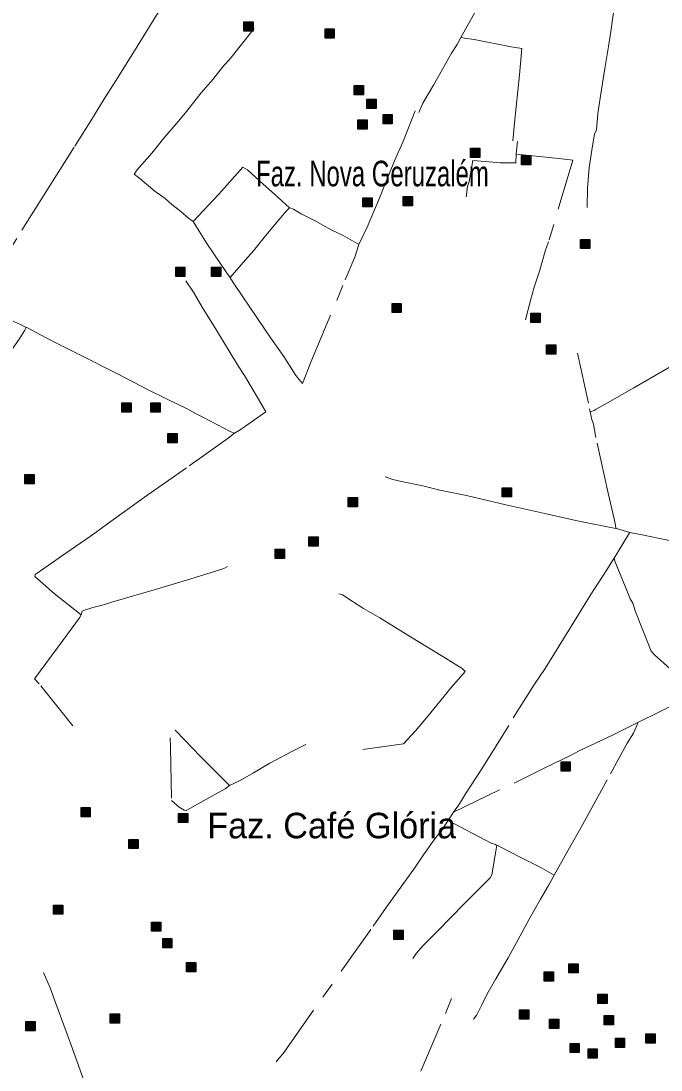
# Model space of a CAD drawing. Extents: x 393.5 to 446.9, y 8064.8 to 8120.4.
# Drawn here: x 428.9 to 432.91, y 8076.18 to 8082.75 of the extents above; entities that cross this region are included whole.
import ezdxf

# ---------------------------------------------------------------- set-up
doc = ezdxf.new("R2010")
doc.units = 0
doc.header["$LTSCALE"] = 0.064
doc.linetypes.add('DOT_DASHED', pattern=[7.7, 5, -1.2, 0.3, -1.2])
doc.layers.add('2', color=7, linetype='Continuous', lineweight=25)
doc.layers.add('22', color=7, linetype='DOT_DASHED', lineweight=13)
doc.layers.add('61', color=7, linetype='Continuous')

msp = doc.modelspace()

# ---------------------------------------------------------------- hatches: boundary and pattern name
at = {"layer": '2'}
for points in [[(430.2985, 8082.7404), (430.3565, 8082.7404), (430.3565, 8082.6824), (430.2985, 8082.6824)], [(430.8062, 8082.697), (430.8642, 8082.697), (430.8642, 8082.639), (430.8062, 8082.639)], [(430.9884, 8082.3419), (431.0464, 8082.3419), (431.0464, 8082.2839), (430.9884, 8082.2839)], [(431.0671, 8082.2575), (431.1251, 8082.2575), (431.1251, 8082.1995), (431.0671, 8082.1995)], [(431.1692, 8082.1613), (431.2272, 8082.1613), (431.2272, 8082.1033), (431.1692, 8082.1033)], [(431.0109, 8082.1278), (431.0689, 8082.1278), (431.0689, 8082.0698), (431.0109, 8082.0698)], [(431.7169, 8081.9496), (431.7749, 8081.9496), (431.7749, 8081.8916), (431.7169, 8081.8916)], [(432.0365, 8081.9048), (432.0945, 8081.9048), (432.0945, 8081.8468), (432.0365, 8081.8468)], [(431.0433, 8081.6399), (431.1013, 8081.6399), (431.1013, 8081.5819), (431.0433, 8081.5819)], [(431.2959, 8081.6468), (431.3539, 8081.6468), (431.3539, 8081.5888), (431.2959, 8081.5888)], [(432.4052, 8081.379), (432.4632, 8081.379), (432.4632, 8081.321), (432.4052, 8081.321)], [(429.8713, 8081.2049), (429.9293, 8081.2049), (429.9293, 8081.1469), (429.8713, 8081.1469)], [(430.0958, 8081.2046), (430.1538, 8081.2046), (430.1538, 8081.1466), (430.0958, 8081.1466)], [(431.2253, 8080.9782), (431.2833, 8080.9782), (431.2833, 8080.9202), (431.2253, 8080.9202)], [(432.095, 8080.9158), (432.153, 8080.9158), (432.153, 8080.8578), (432.095, 8080.8578)], [(432.193, 8080.719), (432.251, 8080.719), (432.251, 8080.661), (432.193, 8080.661)], [(429.5337, 8080.355), (429.5917, 8080.355), (429.5917, 8080.297), (429.5337, 8080.297)], [(429.7162, 8080.3548), (429.7742, 8080.3548), (429.7742, 8080.2968), (429.7162, 8080.2968)], [(429.8217, 8080.1627), (429.8797, 8080.1627), (429.8797, 8080.1047), (429.8217, 8080.1047)], [(428.9274, 8079.9055), (428.9854, 8079.9055), (428.9854, 8079.8475), (428.9274, 8079.8475)], [(431.9156, 8079.8236), (431.9736, 8079.8236), (431.9736, 8079.7656), (431.9156, 8079.7656)], [(430.9513, 8079.7613), (431.0093, 8079.7613), (431.0093, 8079.7033), (430.9513, 8079.7033)], [(430.7054, 8079.5158), (430.7634, 8079.5158), (430.7634, 8079.4578), (430.7054, 8079.4578)], [(430.4949, 8079.4389), (430.5529, 8079.4389), (430.5529, 8079.3809), (430.4949, 8079.3809)], [(432.2833, 8078.1064), (432.3413, 8078.1064), (432.3413, 8078.0484), (432.2833, 8078.0484)], [(429.279, 8077.8199), (429.337, 8077.8199), (429.337, 8077.7619), (429.279, 8077.7619)], [(429.8898, 8077.784), (429.9478, 8077.784), (429.9478, 8077.726), (429.8898, 8077.726)], [(429.5787, 8077.621), (429.6367, 8077.621), (429.6367, 8077.563), (429.5787, 8077.563)], [(429.106, 8077.2097), (429.164, 8077.2097), (429.164, 8077.1517), (429.106, 8077.1517)], [(429.7209, 8077.1034), (429.7789, 8077.1034), (429.7789, 8077.0454), (429.7209, 8077.0454)], [(431.2376, 8077.0524), (431.2956, 8077.0524), (431.2956, 8076.9944), (431.2376, 8076.9944)], [(429.7901, 8077.0005), (429.8481, 8077.0005), (429.8481, 8076.9425), (429.7901, 8076.9425)], [(429.9385, 8076.8501), (429.9965, 8076.8501), (429.9965, 8076.7921), (429.9385, 8076.7921)], [(432.3325, 8076.8425), (432.3905, 8076.8425), (432.3905, 8076.7845), (432.3325, 8076.7845)], [(432.1778, 8076.7912), (432.2358, 8076.7912), (432.2358, 8076.7332), (432.1778, 8076.7332)], [(432.5131, 8076.6506), (432.5711, 8076.6506), (432.5711, 8076.5926), (432.5131, 8076.5926)], [(432.0239, 8076.5537), (432.0819, 8076.5537), (432.0819, 8076.4957), (432.0239, 8076.4957)], [(429.4609, 8076.5278), (429.5189, 8076.5278), (429.5189, 8076.4698), (429.4609, 8076.4698)], [(432.2117, 8076.4948), (432.2697, 8076.4948), (432.2697, 8076.4368), (432.2117, 8076.4368)], [(432.5528, 8076.5183), (432.6108, 8076.5183), (432.6108, 8076.4603), (432.5528, 8076.4603)], [(428.9342, 8076.4799), (428.9922, 8076.4799), (428.9922, 8076.4219), (428.9342, 8076.4219)], [(432.6234, 8076.3761), (432.6814, 8076.3761), (432.6814, 8076.3181), (432.6234, 8076.3181)], [(432.814, 8076.4026), (432.872, 8076.4026), (432.872, 8076.3446), (432.814, 8076.3446)], [(432.3397, 8076.3433), (432.3977, 8076.3433), (432.3977, 8076.2853), (432.3397, 8076.2853)], [(432.452, 8076.3083), (432.51, 8076.3083), (432.51, 8076.2503), (432.452, 8076.2503)]]:
    msp.add_hatch(color=256, dxfattribs=at).paths.add_polyline_path(points)

# ---------------------------------------------------------------- linework, layer by layer
for points in [[(430.2985, 8082.7404), (430.3565, 8082.7404), (430.3565, 8082.6824), (430.2985, 8082.6824)], [(430.8062, 8082.697), (430.8642, 8082.697), (430.8642, 8082.639), (430.8062, 8082.639)], [(430.9884, 8082.3419), (431.0464, 8082.3419), (431.0464, 8082.2839), (430.9884, 8082.2839)], [(431.0671, 8082.2575), (431.1251, 8082.2575), (431.1251, 8082.1995), (431.0671, 8082.1995)], [(431.1692, 8082.1613), (431.2272, 8082.1613), (431.2272, 8082.1033), (431.1692, 8082.1033)], [(431.0109, 8082.1278), (431.0689, 8082.1278), (431.0689, 8082.0698), (431.0109, 8082.0698)], [(431.7169, 8081.9496), (431.7749, 8081.9496), (431.7749, 8081.8916), (431.7169, 8081.8916)], [(432.0365, 8081.9048), (432.0945, 8081.9048), (432.0945, 8081.8468), (432.0365, 8081.8468)], [(431.0433, 8081.6399), (431.1013, 8081.6399), (431.1013, 8081.5819), (431.0433, 8081.5819)], [(431.2959, 8081.6468), (431.3539, 8081.6468), (431.3539, 8081.5888), (431.2959, 8081.5888)], [(432.4052, 8081.379), (432.4632, 8081.379), (432.4632, 8081.321), (432.4052, 8081.321)], [(429.8713, 8081.2049), (429.9293, 8081.2049), (429.9293, 8081.1469), (429.8713, 8081.1469)], [(430.0958, 8081.2046), (430.1538, 8081.2046), (430.1538, 8081.1466), (430.0958, 8081.1466)], [(431.2253, 8080.9782), (431.2833, 8080.9782), (431.2833, 8080.9202), (431.2253, 8080.9202)], [(432.095, 8080.9158), (432.153, 8080.9158), (432.153, 8080.8578), (432.095, 8080.8578)], [(432.193, 8080.719), (432.251, 8080.719), (432.251, 8080.661), (432.193, 8080.661)], [(429.5337, 8080.355), (429.5917, 8080.355), (429.5917, 8080.297), (429.5337, 8080.297)], [(429.7162, 8080.3548), (429.7742, 8080.3548), (429.7742, 8080.2968), (429.7162, 8080.2968)], [(429.8217, 8080.1627), (429.8797, 8080.1627), (429.8797, 8080.1047), (429.8217, 8080.1047)], [(428.9274, 8079.9055), (428.9854, 8079.9055), (428.9854, 8079.8475), (428.9274, 8079.8475)], [(431.9156, 8079.8236), (431.9736, 8079.8236), (431.9736, 8079.7656), (431.9156, 8079.7656)], [(430.9513, 8079.7613), (431.0093, 8079.7613), (431.0093, 8079.7033), (430.9513, 8079.7033)], [(430.7054, 8079.5158), (430.7634, 8079.5158), (430.7634, 8079.4578), (430.7054, 8079.4578)], [(430.4949, 8079.4389), (430.5529, 8079.4389), (430.5529, 8079.3809), (430.4949, 8079.3809)], [(432.2833, 8078.1064), (432.3413, 8078.1064), (432.3413, 8078.0484), (432.2833, 8078.0484)], [(429.279, 8077.8199), (429.337, 8077.8199), (429.337, 8077.7619), (429.279, 8077.7619)], [(429.8898, 8077.784), (429.9478, 8077.784), (429.9478, 8077.726), (429.8898, 8077.726)], [(429.5787, 8077.621), (429.6367, 8077.621), (429.6367, 8077.563), (429.5787, 8077.563)], [(429.106, 8077.2097), (429.164, 8077.2097), (429.164, 8077.1517), (429.106, 8077.1517)], [(429.7209, 8077.1034), (429.7789, 8077.1034), (429.7789, 8077.0454), (429.7209, 8077.0454)], [(431.2376, 8077.0524), (431.2956, 8077.0524), (431.2956, 8076.9944), (431.2376, 8076.9944)], [(429.7901, 8077.0005), (429.8481, 8077.0005), (429.8481, 8076.9425), (429.7901, 8076.9425)], [(429.9385, 8076.8501), (429.9965, 8076.8501), (429.9965, 8076.7921), (429.9385, 8076.7921)], [(432.3325, 8076.8425), (432.3905, 8076.8425), (432.3905, 8076.7845), (432.3325, 8076.7845)], [(432.1778, 8076.7912), (432.2358, 8076.7912), (432.2358, 8076.7332), (432.1778, 8076.7332)], [(432.5131, 8076.6506), (432.5711, 8076.6506), (432.5711, 8076.5926), (432.5131, 8076.5926)], [(432.0239, 8076.5537), (432.0819, 8076.5537), (432.0819, 8076.4957), (432.0239, 8076.4957)], [(429.4609, 8076.5278), (429.5189, 8076.5278), (429.5189, 8076.4698), (429.4609, 8076.4698)], [(432.2117, 8076.4948), (432.2697, 8076.4948), (432.2697, 8076.4368), (432.2117, 8076.4368)], [(432.5528, 8076.5183), (432.6108, 8076.5183), (432.6108, 8076.4603), (432.5528, 8076.4603)], [(428.9342, 8076.4799), (428.9922, 8076.4799), (428.9922, 8076.4219), (428.9342, 8076.4219)], [(432.6234, 8076.3761), (432.6814, 8076.3761), (432.6814, 8076.3181), (432.6234, 8076.3181)], [(432.814, 8076.4026), (432.872, 8076.4026), (432.872, 8076.3446), (432.814, 8076.3446)], [(432.3397, 8076.3433), (432.3977, 8076.3433), (432.3977, 8076.2853), (432.3397, 8076.2853)], [(432.452, 8076.3083), (432.51, 8076.3083), (432.51, 8076.2503), (432.452, 8076.2503)]]:
    msp.add_lwpolyline(points, close=True, dxfattribs=at)
at = {"layer": '22'}
for p, q in [((432.0032, 8081.9134), (432.0101, 8081.9918)), ((432.0032, 8081.9134), (432.0039, 8081.9133)), ((430.2123, 8081.1392), (430.2133, 8081.1377)), ((429.2802, 8079.0273), (429.2796, 8079.0278))]:
    msp.add_line(p, q, dxfattribs=at)
for points in [[(432.0748, 8083.2229), (432.0124, 8083.225), (431.8516, 8083.2263), (431.8325, 8083.2226), (431.8299, 8083.2151), (431.8605, 8083.1458), (431.9039, 8083.0752), (431.8464, 8082.9759), (431.7634, 8082.833), (431.6565, 8082.644)], [(432.5043, 8082.0658), (432.5131, 8082.167), (432.5373, 8082.3168), (432.5564, 8082.4481), (432.5812, 8082.5861), (432.594, 8082.6814), (432.6202, 8082.8604), (432.6463, 8083.0033), (432.6523, 8083.0407)], [(429.3816, 8082.1904), (429.4327, 8082.2714), (429.4986, 8082.3764), (429.6304, 8082.5867), (429.7505, 8082.7831), (429.8016, 8082.8612), (429.8157, 8082.8835)], [(429.9805, 8081.4903), (429.9508, 8081.5126), (429.903, 8081.5531), (429.8463, 8081.5966), (429.806, 8081.6357), (429.7411, 8081.6813), (429.65, 8081.7581), (429.6112, 8081.7871), (429.6276, 8081.8117), (429.7217, 8081.9189), (429.7978, 8082.0131), (429.8868, 8082.1168), (429.9301, 8082.1704), (430.0309, 8082.2957), (430.1041, 8082.3812), (430.1653, 8082.4565), (430.2176, 8082.5188), (430.3154, 8082.6383), (430.3632, 8082.7006)], [(431.3925, 8082.1728), (431.4182, 8082.2328), (431.4854, 8082.3455), (431.5975, 8082.5452), (431.6321, 8082.5986), (431.6565, 8082.644), (431.6592, 8082.6435)], [(431.6592, 8082.6435), (431.679, 8082.6401), (431.7401, 8082.6302), (431.9703, 8082.5847), (432.0375, 8082.5748), (432.0223, 8082.4097), (431.9917, 8082.1092), (431.9856, 8082.04), (431.9825, 8081.9964)], [(428.6286, 8080.9819), (428.6471, 8081.0168), (428.6586, 8081.0341), (428.7066, 8081.1143), (428.9088, 8081.436), (429.0655, 8081.6851), (429.2402, 8081.963), (429.35, 8082.1373), (429.3816, 8082.1904)], [(431.0173, 8081.3475), (431.0706, 8081.4554), (431.1378, 8081.6175), (431.2417, 8081.8705), (431.2927, 8081.9872), (431.3558, 8082.1473), (431.3701, 8082.1849)], [(432.446, 8081.5796), (432.4478, 8081.7005), (432.4592, 8081.8287), (432.4807, 8081.9643), (432.4934, 8082.0374), (432.5043, 8082.0658)], [(432.0032, 8081.9134), (432.0008, 8081.8579), (431.903, 8081.8593), (431.8109, 8081.8677), (431.7318, 8081.8719), (431.7073, 8081.7406), (431.6987, 8081.7099), (431.6886, 8081.6457)], [(432.0039, 8081.9133), (432.2686, 8081.8858), (432.3578, 8081.8747), (432.2051, 8081.3637), (432.1835, 8081.3051), (432.1504, 8081.1864), (432.1159, 8081.0789), (432.0943, 8081.0035), (432.0612, 8080.875)], [(429.9805, 8081.4903), (430.141, 8081.6626), (430.2918, 8081.8321), (430.3208, 8081.8154), (430.4193, 8081.7256), (430.4895, 8081.6618), (430.5582, 8081.5995), (430.5845, 8081.5775)], [(430.2123, 8081.1392), (430.3083, 8081.2501), (430.359, 8081.308), (430.4247, 8081.3906), (430.4934, 8081.4732), (430.5651, 8081.5572), (430.5842, 8081.5772), (430.5845, 8081.5775), (430.5854, 8081.5771)], [(430.5854, 8081.5771), (430.6084, 8081.5674), (430.6562, 8081.5399), (430.7398, 8081.4978), (430.8443, 8081.4384), (430.919, 8081.4022), (431.0069, 8081.3533), (431.0166, 8081.3479), (431.0167, 8081.3478), (431.0173, 8081.3475)], [(429.9805, 8081.4903), (430.0659, 8081.3536), (430.1899, 8081.1711), (430.2123, 8081.1392)], [(430.2133, 8081.1377), (430.2432, 8081.0908), (430.3799, 8080.8887), (430.4665, 8080.7598), (430.5486, 8080.6453), (430.6233, 8080.5265), (430.6651, 8080.4758), (430.7172, 8080.6094), (430.9329, 8081.1252), (430.9919, 8081.2678), (431.0173, 8081.3475)], [(430.3017, 8080.5258), (430.2582, 8080.5937), (430.1271, 8080.8097), (430.038, 8080.9549), (429.9836, 8081.0474), (429.9353, 8081.1194)], [(428.6314, 8080.9802), (428.6503, 8080.9683), (428.6797, 8080.9571), (428.8631, 8080.8628), (428.899, 8080.846), (428.9363, 8080.8277), (428.9389, 8080.8264)], [(428.2665, 8079.8096), (428.3724, 8079.9669), (428.5198, 8080.1884), (428.5631, 8080.258), (428.6468, 8080.3831), (428.7062, 8080.4803), (428.7854, 8080.5944), (428.825, 8080.658), (428.8952, 8080.7607), (428.9274, 8080.8112), (428.9358, 8080.8268), (428.9363, 8080.8277)], [(428.9389, 8080.8264), (428.9707, 8080.8099), (429.0251, 8080.7811), (429.1204, 8080.7319), (429.2593, 8080.6611), (429.5061, 8080.5369), (429.7034, 8080.4355), (429.8135, 8080.3803), (429.9428, 8080.3168), (429.9998, 8080.2868), (430.0406, 8080.2663), (430.09, 8080.2408), (430.2175, 8080.1744), (430.2397, 8080.1659)], [(432.3871, 8080.6659), (432.4622, 8080.3182), (432.4662, 8080.299), (432.4664, 8080.2979)], [(433.0631, 8080.6323), (433.0037, 8080.6044), (432.9669, 8080.5809), (432.7391, 8080.4492), (432.5747, 8080.3559), (432.5036, 8080.3153), (432.4911, 8080.3072), (432.4681, 8080.2985), (432.4664, 8080.2979)], [(430.2397, 8080.1659), (430.2812, 8080.1904), (430.4346, 8080.2984), (430.3889, 8080.3788), (430.3017, 8080.5258)], [(432.6264, 8079.5686), (432.6244, 8079.5891), (432.6164, 8079.6282), (432.5777, 8079.79), (432.5012, 8080.1378), (432.4859, 8080.2216), (432.4747, 8080.2573), (432.472, 8080.2695), (432.4664, 8080.2979)], [(429.2796, 8079.0278), (429.1114, 8079.161), (428.9901, 8079.2666), (428.9914, 8079.281), (429.052, 8079.3218), (429.1572, 8079.3951), (429.3644, 8079.5386), (429.4448, 8079.5974), (429.6768, 8079.7637), (429.9551, 8079.9606), (430.0182, 8080.0038), (430.1506, 8080.0986), (430.2001, 8080.1334), (430.2397, 8080.1659)], [(432.3936, 8079.6137), (432.1821, 8079.6628), (431.937, 8079.717), (431.692, 8079.7741), (431.5237, 8079.8073), (431.4179, 8079.8348), (431.2846, 8079.863), (431.231, 8079.8745), (431.1833, 8079.8919)], [(432.7164, 8079.1272), (432.6872, 8079.2003), (432.6209, 8079.3643), (432.6151, 8079.3827), (432.615, 8079.3831), (432.7116, 8079.5412), (432.7128, 8079.5432), (432.6294, 8079.5677), (432.6264, 8079.5686), (432.3936, 8079.6137)], [(432.7128, 8079.5432), (432.7918, 8079.5288), (433.0025, 8079.4847), (433.0889, 8079.4645), (433.3319, 8079.4102), (433.3731, 8079.407), (433.3764, 8079.4278), (433.3795, 8079.4393)], [(431.6103, 8077.7923), (431.6484, 8077.844), (431.6856, 8077.9061), (431.7884, 8078.0622), (431.9843, 8078.3823), (432.1176, 8078.594), (432.1832, 8078.6923), (432.3418, 8078.9488), (432.4646, 8079.1475), (432.5696, 8079.3102), (432.6069, 8079.3694), (432.615, 8079.3831)], [(429.2802, 8079.0273), (429.2861, 8079.05), (429.2942, 8079.0552), (429.3524, 8079.0723), (429.42, 8079.0907), (429.4782, 8079.1078), (429.7509, 8079.1885), (429.9607, 8079.2503), (430.0595, 8079.2831), (430.1727, 8079.3174), (430.1957, 8079.3292)], [(431.0425, 8078.1841), (431.2962, 8078.2199), (431.3725, 8078.3004), (431.4405, 8078.3825), (431.5972, 8078.5749), (431.6835, 8078.6731), (431.6636, 8078.6908), (431.5773, 8078.7455), (431.5432, 8078.7674), (431.3414, 8078.8893), (431.1489, 8079.0084), (431.0477, 8079.068), (430.983, 8079.1098), (430.915, 8079.1517), (430.8918, 8079.1597)], [(432.7649, 8078.3531), (433.0226, 8078.4805), (433.1288, 8078.5321), (432.9658, 8078.6885), (432.8687, 8078.7774), (432.8472, 8078.8007), (432.7912, 8078.9419), (432.748, 8079.0518), (432.7316, 8079.1009), (432.7164, 8079.1272)], [(429.2273, 8078.3324), (429.0162, 8078.5963), (428.9878, 8078.6265), (429.1651, 8078.8668), (429.2686, 8079.0079), (429.2802, 8079.0273)], [(432.2402, 8077.3973), (432.3279, 8077.553), (432.4176, 8077.713), (432.5927, 8078.0321), (432.6981, 8078.2232), (432.7366, 8078.2872), (432.7586, 8078.3352), (432.7649, 8078.3531)], [(432.3934, 8078.1729), (432.6101, 8078.2767), (432.7649, 8078.3531)], [(429.8674, 8078.3053), (429.9282, 8078.2422), (430.0247, 8078.1426), (430.2091, 8077.9595)], [(429.836, 8078.2565), (429.8381, 8078.1995), (429.8444, 8077.8639), (429.8926, 8077.8232), (429.924, 8077.8049), (429.9345, 8077.8008), (429.989, 8077.8313), (430.1022, 8077.8944), (430.1819, 8077.9371), (430.2091, 8077.9595)], [(430.2091, 8077.9595), (430.2741, 8077.99), (430.358, 8078.0388), (430.4607, 8078.0978), (430.599, 8078.171), (430.685, 8078.2158)], [(431.6103, 8077.7923), (432.0102, 8077.9838), (432.177, 8078.0673), (432.3474, 8078.1491), (432.3934, 8078.1729)], [(431.4438, 8077.554), (431.4761, 8077.6018), (431.5436, 8077.6885), (431.5764, 8077.7392)], [(431.5761, 8077.7387), (431.5764, 8077.7392), (431.6103, 8077.7923)], [(431.5764, 8077.7392), (431.8455, 8077.598), (431.8725, 8077.5894), (431.873, 8077.5892)], [(430.5, 8076.2277), (430.5496, 8076.2894), (431.1074, 8077.077), (431.1888, 8077.1945), (431.2914, 8077.3359), (431.3609, 8077.4342), (431.4225, 8077.5247), (431.4438, 8077.554)], [(431.3558, 8076.8746), (431.3757, 8076.906), (431.4215, 8076.9575), (431.5149, 8077.05), (431.5901, 8077.1282), (431.6817, 8077.2207), (431.8401, 8077.3798), (431.8511, 8077.3993), (431.8758, 8077.5478), (431.882, 8077.5848)], [(432.2402, 8077.3973), (432.1533, 8077.4469), (432.0232, 8077.5127), (431.906, 8077.5731), (431.882, 8077.5848), (431.8761, 8077.5877), (431.873, 8077.5892)], [(431.735, 8076.4942), (431.757, 8076.5227), (431.7881, 8076.5849), (431.8193, 8076.6489), (431.8743, 8076.7485), (431.9525, 8076.8786), (432.0405, 8077.0404), (432.0845, 8077.1204), (432.1541, 8077.2466), (432.2054, 8077.332), (432.2249, 8077.3688), (432.2402, 8077.3973)], [(429.0439, 8076.7867), (429.0575, 8076.7579), (429.086, 8076.6918), (429.1206, 8076.5922), (429.1866, 8076.4179), (429.2258, 8076.3088), (429.3233, 8076.0354), (429.3663, 8075.9096), (429.4022, 8075.8088), (429.4183, 8075.768), (429.4282, 8075.7428), (429.4492, 8075.6575)], [(431.2585, 8075.7987), (431.4061, 8076.1701), (431.5599, 8076.5309), (431.5976, 8076.6253)]]:
    msp.add_lwpolyline(points, dxfattribs=at)

# ---------------------------------------------------------------- texts
at = {"layer": '61', "width": 0.7}
msp.add_text('Faz. Nova Geruzalém', height=0.16, dxfattribs=at).set_placement((430.3745, 8081.7113))
at = {"layer": '61'}
msp.add_text('Faz. Café Glória', height=0.16, dxfattribs=at).set_placement((430.069, 8077.6278))

doc.saveas('drawing.dxf')
